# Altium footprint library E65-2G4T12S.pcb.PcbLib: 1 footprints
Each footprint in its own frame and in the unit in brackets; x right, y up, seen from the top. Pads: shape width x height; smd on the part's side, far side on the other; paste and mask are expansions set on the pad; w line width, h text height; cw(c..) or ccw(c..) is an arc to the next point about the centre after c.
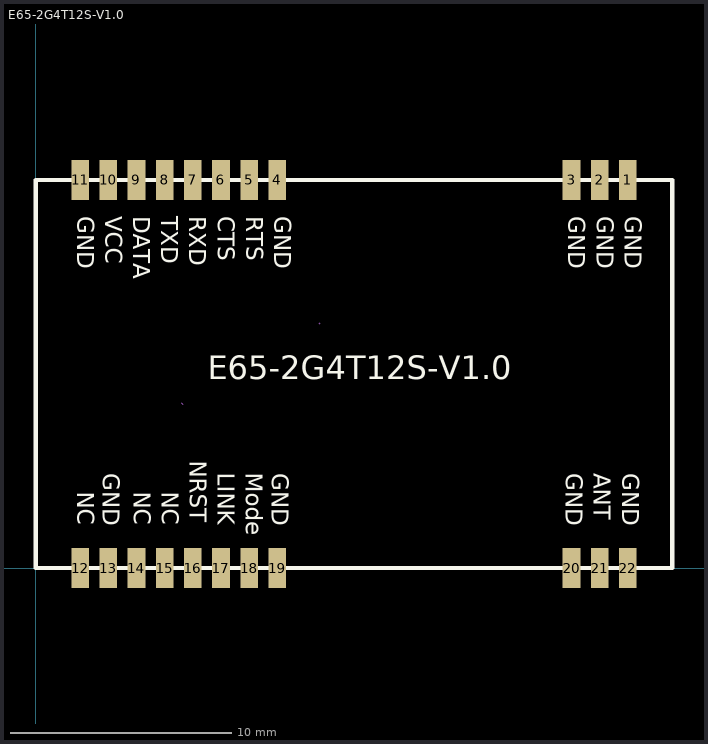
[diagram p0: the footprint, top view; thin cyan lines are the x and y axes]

## E65-2G4T12S-V1.0 [mm] "26*16mm"
pads (22):
  rect 0.8x1.8 smd: 1(26.7,17.5) 2(25.43,17.5) 3(24.16,17.5) 4(10.89,17.5) 5(9.62,17.5) 6(8.35,17.5) 7(7.08,17.5) 8(5.81,17.5) 9(4.54,17.5) 10(3.27,17.5) 11(2,17.5) 12(2,0) 13(3.27,0) 14(4.54,0) 15(5.81,0) 16(7.08,0) 17(8.35,0) 18(9.62,0) 19(10.89,0) 20(24.16,0) 21(25.43,0) 22(26.7,0)
Top Overlay:
  lines w0.2: 0,0 0,17.5 28.7,17.5 28.7,0 0,0
  text "GND" at 2.764,4.281 h1.3
  text "E65-2G4T12S-V1.0" at 7.747,8.148 h1.8
  text "NRST" at 6.701,4.83 h1.3
  text "RTS" at 9.236,15.869 h1.3
  text "CTS" at 7.966,15.869 h1.3
  text "DATA" at 4.141,15.869 h1.3
  text "VCC" at 2.886,15.868 h1.3
  text "GND" at 1.616,15.869 h1.3
  text "GND" at 10.506,15.869 h1.3
  text "GND" at 23.776,15.869 h1.3
  text "GND" at 25.046,15.869 h1.3
  text "GND" at 26.316,15.869 h1.3
  text "TXD" at 5.411,15.869 h1.3
  text "RXD" at 6.681,15.869 h1.3
  text "GND" at 10.384,4.281 h1.3
  text "LINK" at 7.967,4.293 h1.3
  text "Mode" at 9.213,4.286 h1.3
  text "GND" at 23.654,4.281 h1.3
  text "GND" at 26.194,4.281 h1.3
  text "ANT" at 24.91,4.281 h1.3
  text "NC" at 4.159,3.442 h1.3
  text "NC" at 5.429,3.442 h1.3
  text "NC" at 1.619,3.442 h1.3
Mechanical 15:
  lines w0.003: 6.567,7.443 6.618,7.392 ; 12.756,11.056 12.807,11.005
